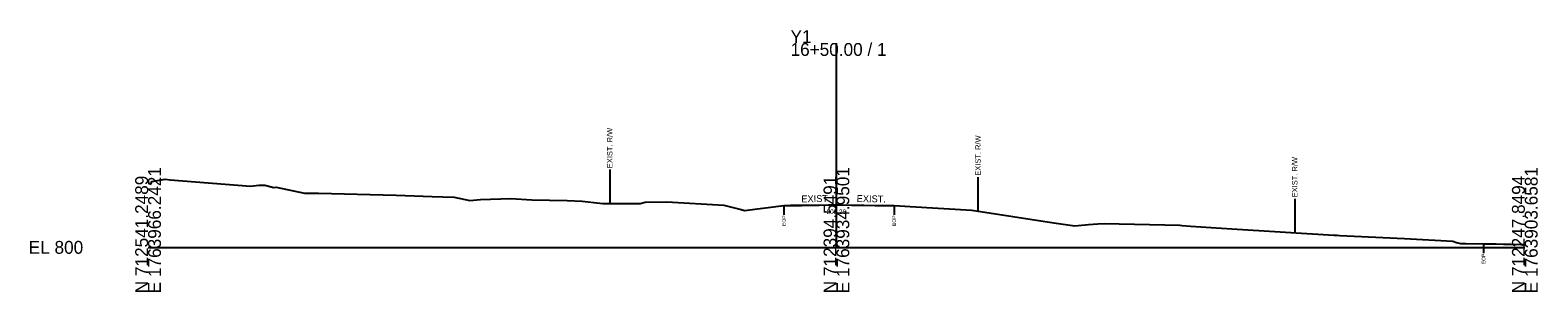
# Model space of a CAD drawing. Extents: x -26 to 1303, y -10 to 9524.
# Drawn here: x -25.7 to 302.8, y 6490.3 to 6547.3 of the extents above; entities that cross this region are included whole.
import ezdxf

# ---------------------------------------------------------------- set-up
doc = ezdxf.new("R2010")
doc.units = 0
for name, color, linetype in [('Default', 7, 'Continuous'), ('Exist Cross Section Cell', 7, 'Continuous'), ('Exist XS Center Line Elevation Label', 7, 'Continuous'), ('Exist XS Ground Line', 7, 'Continuous'), ('Old_Level_10', 7, 'Continuous'), ('Prop CMT Pvmt Surface Overlay', 7, 'Continuous'), ('Prop XS SE Text', 7, 'Continuous')]:
    doc.layers.add(name, color=color, linetype=linetype)

msp = doc.modelspace()

# ---------------------------------------------------------------- linework, layer by layer
at = {"layer": 'Exist Cross Section Cell'}
for p, q in [((150, 6500), (150, 6544.51)), ((0, 6500), (150, 6500)), ((150, 6500), (300, 6500))]:
    msp.add_line(p, q, dxfattribs=at)
at = {"layer": 'Exist XS Ground Line'}
msp.add_lwpolyline([(0, 6513.97), (0.66, 6513.93), (0.8, 6514.31), (3.7, 6514.82), (4.81, 6514.73), (22.29, 6513.36), (24.17, 6513.55), (25.47, 6513.53), (27.38, 6513.05), (27.89, 6513.12), (34.1, 6511.79), (37.11, 6511.8), (54.07, 6511.34), (61.94, 6511.1), (64.22, 6511.01), (66.67, 6510.95), (70.11, 6510.2), (72.43, 6510.44), (79.07, 6510.63), (83.65, 6510.36), (91.31, 6510.19), (94.6, 6510.04), (98.44, 6509.66), (99.12, 6509.58), (99.83, 6509.55), (104.91, 6509.52), (107.24, 6509.57), (108.29, 6509.86), (113.04, 6509.91), (125.48, 6509.17), (129.21, 6508.25), (129.99, 6508.04), (138.57, 6509.1), (139.97, 6509.16), (141.15, 6509.16), (143.26, 6509.17), (143.77, 6509.17), (145.36, 6509.21), (145.7, 6509.21), (146.23, 6509.22), (148.26, 6509.25), (150, 6509.26), (150.68, 6509.27), (153.37, 6509.22), (153.79, 6509.22), (155.98, 6509.21), (158.49, 6509.15), (160.03, 6509.16), (160.54, 6509.15), (161, 6509.15), (162.56, 6509.1), (166.04, 6508.91), (179.49, 6508.11), (197.36, 6505.31), (201.92, 6504.68), (204.96, 6504.96), (206.95, 6505.15), (208.36, 6505.22), (224.8, 6504.8), (225.36, 6504.76), (227.12, 6504.62), (236.14, 6504.03), (258.39, 6502.68), (259.09, 6502.65), (259.69, 6502.61), (273.81, 6501.93), (284.31, 6501.31), (285.14, 6501.07), (285.96, 6500.83), (287.12, 6500.82), (291.02, 6500.78), (292.11, 6500.77), (292.76, 6500.75), (293.74, 6500.73), (295.36, 6500.71), (297.06, 6500.69), (299.16, 6500.65), (299.56, 6500.64), (300, 6500.64)], dxfattribs=at)
at = {"layer": 'Old_Level_10'}
for p, q in [((100.6, 6516.94), (100.6, 6509.54)), ((180.84, 6515.3), (180.84, 6507.9)), ((138.57, 6509.1), (138.57, 6507.05)), ((162.56, 6509.1), (162.56, 6507.05)), ((249.87, 6510.6), (249.87, 6503.2)), ((291.02, 6500.78), (291.02, 6498.73))]:
    msp.add_line(p, q, dxfattribs=at)
at = {"layer": 'Prop CMT Pvmt Surface Overlay'}
for p, q in [((138.57, 6509.05), (150, 6509.25)), ((150, 6509.25), (162.56, 6509.08))]:
    msp.add_line(p, q, dxfattribs=at)

# ---------------------------------------------------------------- texts
at = {"layer": 'Default'}
msp.add_text('-', height=0.0001, dxfattribs=at).set_placement((0, 6500))
at = {"layer": 'Exist Cross Section Cell'}
for s, p in [('Y1', (140, 6544.51)), ('16+50.00 / 1', (140, 6541.71)), ('EL 800', (-26, 6498.6))]:
    msp.add_text(s, height=2.8, dxfattribs=at).set_placement(p)
for s, p in [('N 712541.2489', (0, 6490)), ('E 1763966.2421', (2.8, 6490)), ('N 712394.5491', (150, 6490)), ('E 1763934.9501', (152.8, 6490)), ('N 712247.8494', (300, 6490)), ('E 1763903.6581', (302.8, 6490))]:
    msp.add_text(s, height=2.8, rotation=90, dxfattribs=at).set_placement(p)
at = {"layer": 'Exist XS Center Line Elevation Label'}
msp.add_text('809.26', height=1, dxfattribs=at).set_placement((147.86, 6507.26))
at = {"layer": 'Old_Level_10'}
for s, height, p in [('EXIST. R/W', 1.181, (101.19, 6517.25)), ('EXIST. R/W', 1.181, (181.43, 6515.6)), ('EXIST. R/W', 1.181, (250.46, 6510.9)), ('EOP', 0.787, (138.97, 6504.65)), ('EOP', 0.787, (162.95, 6504.65)), ('EOP', 0.787, (291.41, 6496.33))]:
    msp.add_text(s, height=height, rotation=90, dxfattribs=at).set_placement(p)
at = {"layer": 'Prop XS SE Text'}
for rotation, p in [(1.1458, (142.37, 6509.79)), (358.8542, (154.41, 6509.89))]:
    msp.add_text('EXIST.', height=1.5, rotation=rotation, dxfattribs=at).set_placement(p)

doc.saveas('drawing.dxf')
